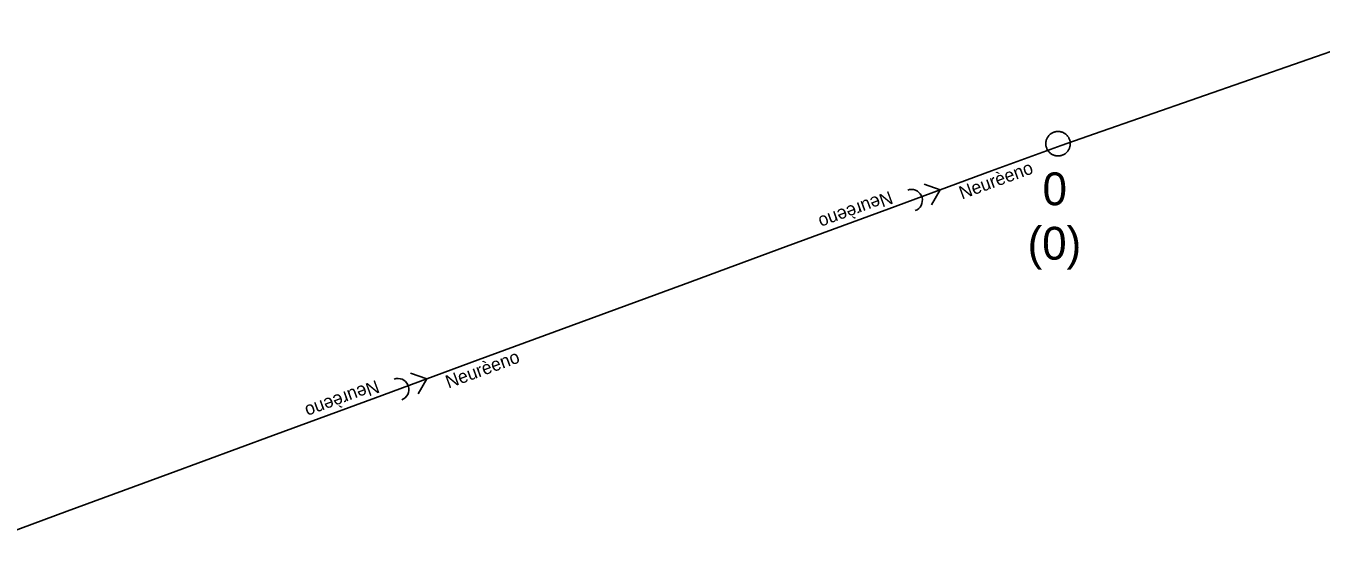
# Model space of a CAD drawing. Extents: x -606452 to -604459, y -1157823 to -1156972.
# Drawn here: x -605832.28 to -605805.82, y -1157744.89 to -1157734.21 of the extents above; entities that cross this region are included whole.
import ezdxf

# ---------------------------------------------------------------- set-up
doc = ezdxf.new("R2010")
doc.units = 0
doc.layers.add('Stoka', color=7, linetype='Continuous')
doc.layers.add('Vstupní šachta stoky', color=7, linetype='Continuous')

msp = doc.modelspace()

# ---------------------------------------------------------------- linework, layer by layer
at = {"layer": 'Stoka'}
for points in [[(-605804.114, -1157734.205), (-605806.226, -1157734.94)], [(-605806.226, -1157734.94), (-605808.338, -1157735.674)], [(-605808.338, -1157735.674), (-605810.451, -1157736.408)], [(-605810.451, -1157736.408), (-605811.133, -1157736.645)], [(-605811.133, -1157736.645), (-605812.553, -1157737.168)], [(-605812.553, -1157737.168), (-605814.652, -1157737.94)], [(-605813.602, -1157737.553), (-605813.932, -1157737.437)], [(-605814.267, -1157737.56), (-605814.227, -1157737.549), (-605814.186, -1157737.546), (-605814.145, -1157737.55), (-605814.106, -1157737.562), (-605814.069, -1157737.581), (-605814.037, -1157737.607), (-605814.009, -1157737.638), (-605813.988, -1157737.673), (-605813.974, -1157737.712), (-605813.967, -1157737.753), (-605813.968, -1157737.794), (-605813.976, -1157737.834), (-605813.992, -1157737.872), (-605814.014, -1157737.907), (-605814.042, -1157737.937), (-605814.075, -1157737.961), (-605814.113, -1157737.979)], [(-605813.601, -1157737.553), (-605813.777, -1157737.857)], [(-605814.652, -1157737.94), (-605816.75, -1157738.713)], [(-605816.75, -1157738.713), (-605818.849, -1157739.485)], [(-605818.849, -1157739.485), (-605820.947, -1157740.258)], [(-605820.947, -1157740.258), (-605823.045, -1157741.03)], [(-605823.045, -1157741.03), (-605825.144, -1157741.803)], [(-605824.759, -1157741.422), (-605824.719, -1157741.411), (-605824.678, -1157741.408), (-605824.637, -1157741.413), (-605824.598, -1157741.425), (-605824.561, -1157741.444), (-605824.529, -1157741.469), (-605824.501, -1157741.5), (-605824.48, -1157741.536), (-605824.466, -1157741.574), (-605824.459, -1157741.615), (-605824.46, -1157741.656), (-605824.468, -1157741.697), (-605824.484, -1157741.735), (-605824.506, -1157741.77), (-605824.534, -1157741.8), (-605824.567, -1157741.824), (-605824.605, -1157741.842)], [(-605824.094, -1157741.415), (-605824.424, -1157741.299)], [(-605824.093, -1157741.416), (-605824.269, -1157741.719)], [(-605825.144, -1157741.803), (-605827.242, -1157742.575)], [(-605827.242, -1157742.575), (-605829.341, -1157743.348)], [(-605829.341, -1157743.348), (-605831.439, -1157744.12)], [(-605831.439, -1157744.12), (-605833.537, -1157744.893)]]:
    msp.add_lwpolyline(points, dxfattribs=at)
at = {"layer": 'Vstupní šachta stoky'}
msp.add_line((-605811.208, -1157736.361), (-605811.195, -1157736.361), dxfattribs=at)
for points in [[(-605811.195, -1157736.361), (-605811.182, -1157736.361), (-605811.169, -1157736.362), (-605811.156, -1157736.364), (-605811.143, -1157736.367), (-605811.13, -1157736.37), (-605811.117, -1157736.373), (-605811.105, -1157736.378), (-605811.093, -1157736.383), (-605811.081, -1157736.389), (-605811.069, -1157736.395), (-605811.058, -1157736.402), (-605811.047, -1157736.41), (-605811.037, -1157736.418), (-605811.027, -1157736.426), (-605811.017, -1157736.435), (-605811.008, -1157736.445), (-605811, -1157736.455), (-605810.992, -1157736.466), (-605810.984, -1157736.477), (-605810.977, -1157736.488), (-605810.971, -1157736.5), (-605810.966, -1157736.512), (-605810.961, -1157736.524), (-605810.956, -1157736.536), (-605810.953, -1157736.549), (-605810.95, -1157736.562), (-605810.948, -1157736.575), (-605810.946, -1157736.588), (-605810.945, -1157736.601), (-605810.945, -1157736.614), (-605810.946, -1157736.628), (-605810.947, -1157736.641), (-605810.949, -1157736.654), (-605810.951, -1157736.667), (-605810.955, -1157736.679), (-605810.958, -1157736.692), (-605810.963, -1157736.704), (-605810.968, -1157736.717), (-605810.974, -1157736.728), (-605810.981, -1157736.74), (-605810.988, -1157736.751), (-605810.995, -1157736.762), (-605811.004, -1157736.772), (-605811.012, -1157736.782), (-605811.022, -1157736.791), (-605811.032, -1157736.8), (-605811.042, -1157736.809), (-605811.052, -1157736.816), (-605811.063, -1157736.824), (-605811.075, -1157736.83), (-605811.087, -1157736.836), (-605811.099, -1157736.842), (-605811.111, -1157736.846), (-605811.123, -1157736.851), (-605811.136, -1157736.854), (-605811.149, -1157736.857), (-605811.162, -1157736.859), (-605811.175, -1157736.86), (-605811.188, -1157736.861), (-605811.202, -1157736.861), (-605811.215, -1157736.86), (-605811.228, -1157736.859), (-605811.241, -1157736.857), (-605811.254, -1157736.854), (-605811.267, -1157736.851), (-605811.279, -1157736.846), (-605811.291, -1157736.842), (-605811.303, -1157736.836), (-605811.315, -1157736.83), (-605811.327, -1157736.824), (-605811.338, -1157736.816), (-605811.348, -1157736.809), (-605811.358, -1157736.8), (-605811.368, -1157736.791), (-605811.378, -1157736.782), (-605811.386, -1157736.772), (-605811.395, -1157736.762), (-605811.402, -1157736.751), (-605811.409, -1157736.74), (-605811.416, -1157736.728), (-605811.422, -1157736.717), (-605811.427, -1157736.704), (-605811.432, -1157736.692), (-605811.435, -1157736.679), (-605811.439, -1157736.667), (-605811.441, -1157736.654), (-605811.443, -1157736.641), (-605811.444, -1157736.628), (-605811.445, -1157736.614), (-605811.445, -1157736.601), (-605811.444, -1157736.588), (-605811.442, -1157736.575), (-605811.44, -1157736.562), (-605811.437, -1157736.549), (-605811.434, -1157736.536), (-605811.429, -1157736.524), (-605811.424, -1157736.512), (-605811.419, -1157736.5), (-605811.413, -1157736.488), (-605811.406, -1157736.477)], [(-605811.406, -1157736.477), (-605811.398, -1157736.466), (-605811.39, -1157736.455), (-605811.382, -1157736.445), (-605811.373, -1157736.435), (-605811.363, -1157736.426), (-605811.353, -1157736.418), (-605811.343, -1157736.41), (-605811.332, -1157736.402), (-605811.321, -1157736.395), (-605811.309, -1157736.389), (-605811.297, -1157736.383), (-605811.285, -1157736.378), (-605811.273, -1157736.373), (-605811.26, -1157736.37), (-605811.247, -1157736.367), (-605811.234, -1157736.364), (-605811.221, -1157736.362), (-605811.208, -1157736.361)]]:
    msp.add_lwpolyline(points, dxfattribs=at)

# ---------------------------------------------------------------- texts
at = {"layer": 'Stoka'}
for rotation, p in [(20.2102, (-605813.158, -1157737.752)), (200.2102, (-605814.635, -1157737.572)), (20.2102, (-605823.65, -1157741.615)), (200.2102, (-605825.127, -1157741.434))]:
    msp.add_text('Neurèeno', height=0.2683, rotation=rotation, dxfattribs=at).set_placement(p)
at = {"layer": 'Vstupní šachta stoky'}
for s, height, p in [('0', 0.671, (-605811.511, -1157737.869)), ('(0)', 0.6708, (-605811.817, -1157738.98))]:
    msp.add_text(s, height=height, dxfattribs=at).set_placement(p)

doc.saveas('drawing.dxf')
